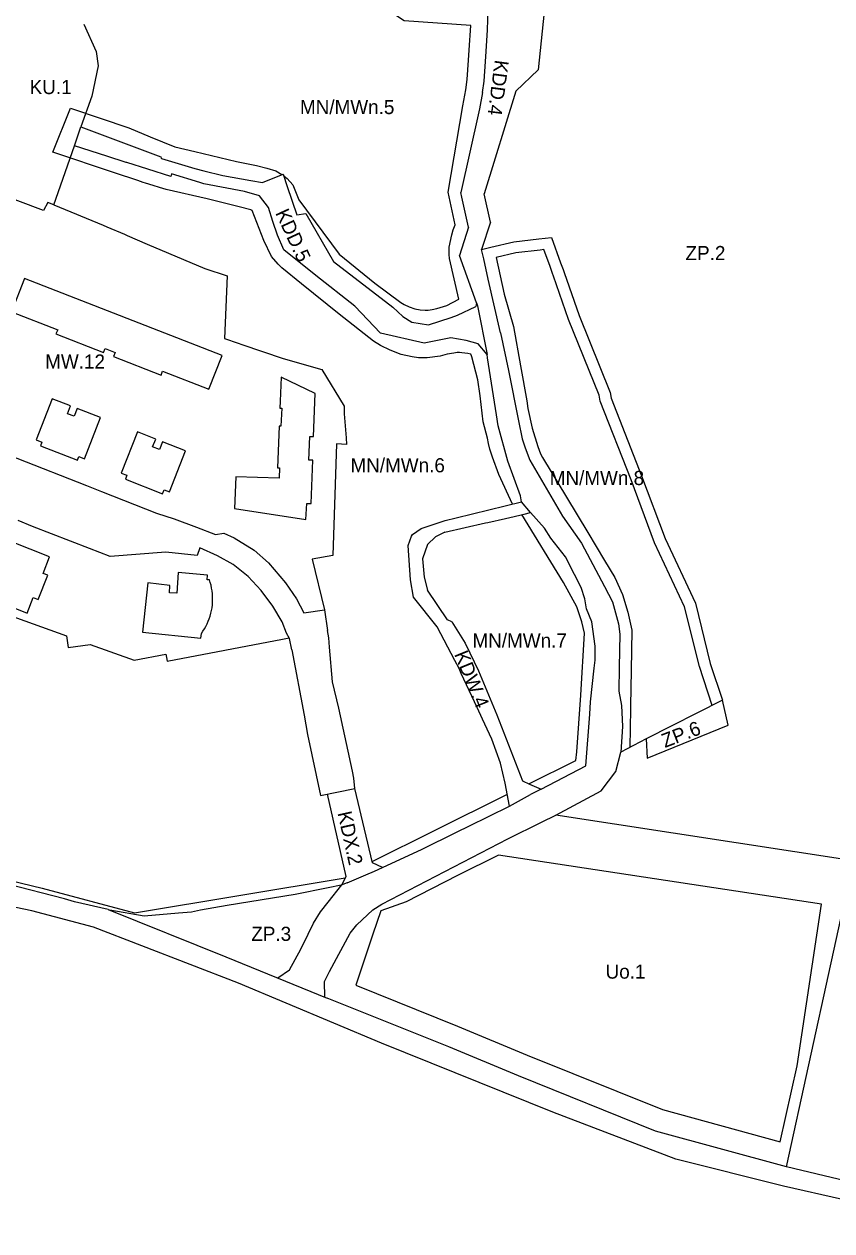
# Model space of a CAD drawing. Extents: x 7427074 to 7428708, y 5545888 to 5547145.
# Drawn here: x 7427601.2 to 7427887.2, y 5545922.5 to 5546349.6 of the extents above; entities that cross this region are included whole.
import ezdxf

# ---------------------------------------------------------------- set-up
doc = ezdxf.new("R2010")
doc.units = 0
for name, color, linetype in [('linie_rozgraniczajace', 7, 'Continuous'), ('linie_zabudowy_nieprzekraczalne', 7, 'Continuous'), ('linie_zabudowy_obowiazujace', 7, 'Continuous'), ('oznaczenia_przeznaczen', 7, 'Continuous')]:
    doc.layers.add(name, color=color, linetype=linetype)

msp = doc.modelspace()

# ---------------------------------------------------------------- linework, layer by layer
at = {"layer": 'linie_rozgraniczajace'}
for p, q in [((7427765.34, 5546347.61), (7427765.55, 5546354.65)), ((7427783.21, 5546333.36), (7427775.36, 5546325.89)), ((7427775.36, 5546325.89), (7427764.1, 5546289.55)), ((7427766.36, 5546279.48), (7427763.23, 5546269.84)), ((7427761.42, 5546250.98), (7427761.19, 5546249.62)), ((7427784.31, 5546078.85), (7427800.15, 5546087.09)), ((7427708.54, 5546077.03), (7427715.12, 5546047.85)), ((7427784.31, 5546078.85), (7427780.51, 5546076.87)), ((7427715.6, 5546045.7), (7427713.44, 5546044.8))]:
    msp.add_line(p, q, dxfattribs=at)
for points in [[(7427796.61, 5546466.79), (7427791.59, 5546414.49), (7427783.21, 5546333.36)], [(7427622.4, 5546349.58), (7427626.69, 5546339.86), (7427627.45, 5546334.8), (7427625.24, 5546324.12), (7427621.3, 5546313.22)], [(7427763.57, 5546325.38), (7427764.08, 5546329.36), (7427764.56, 5546336.41), (7427764.81, 5546339.92), (7427765.34, 5546347.61)], [(7427763.57, 5546325.38), (7427762.45, 5546319.55), (7427762.19, 5546318.5), (7427755.86, 5546289.94)], [(7427663.43, 5546293.51), (7427653.47, 5546296.56), (7427653.2, 5546295.66), (7427645.05, 5546298.22), (7427637.57, 5546300.58), (7427637.31, 5546300.66), (7427630.48, 5546302.84), (7427619.05, 5546306.5), (7427620.59, 5546311.05), (7427621.3, 5546313.22), (7427636.39, 5546307.59), (7427649.59, 5546302.67), (7427649.74, 5546302.14), (7427649.93, 5546302.08), (7427661.68, 5546298.43), (7427664.82, 5546297.67)], [(7427611.7, 5546285.64), (7427619.05, 5546306.5)], [(7427611.7, 5546285.64), (7427609.61, 5546286.47), (7427608.13, 5546283.63), (7427588.87, 5546290.82), (7427583.89, 5546292.85), (7427575.59, 5546296.26)], [(7427664.82, 5546297.67), (7427671.58, 5546296.04), (7427681.51, 5546294.25), (7427685.64, 5546293.55), (7427692.95, 5546296.51), (7427694.39, 5546292.07), (7427697.81, 5546282.09), (7427701.03, 5546282.56), (7427710.78, 5546265.62), (7427731.74, 5546249.35), (7427735.28, 5546246.13), (7427738.53, 5546244.14), (7427744.43, 5546243.1), (7427752.45, 5546245.69), (7427754.69, 5546246.55), (7427761.19, 5546249.62)], [(7427765.2, 5546232.62), (7427762.04, 5546236.48), (7427757.79, 5546237.61), (7427752.3, 5546238.55), (7427742.92, 5546236.65), (7427727.45, 5546240.25), (7427718.34, 5546249.77), (7427704.58, 5546260.65), (7427693.22, 5546269.69), (7427690.96, 5546274.84), (7427689.32, 5546279.73), (7427687.71, 5546284.73), (7427684.63, 5546288.81), (7427679.24, 5546290.32), (7427664.81, 5546293.09), (7427663.43, 5546293.51)], [(7427758.55, 5546277.73), (7427756.16, 5546288.39), (7427755.86, 5546289.94)], [(7427766.36, 5546279.48), (7427764.1, 5546289.55)], [(7427611.7, 5546285.64), (7427629.19, 5546278.47), (7427630.55, 5546277.88), (7427636.72, 5546275.2), (7427637.7, 5546274.77), (7427644.78, 5546271.7), (7427665.21, 5546263.09), (7427673.1, 5546260.46), (7427672.16, 5546238.35), (7427677.06, 5546236.65), (7427678.32, 5546236.22), (7427692.95, 5546231.24), (7427706.64, 5546227.31), (7427714.54, 5546214.32), (7427714.54, 5546211.6), (7427715.24, 5546203.17), (7427715.43, 5546200.75), (7427711.81, 5546201.08), (7427710.51, 5546161.49), (7427703.17, 5546160.22), (7427707.56, 5546142.3)], [(7427758.55, 5546277.73), (7427755.38, 5546267.67)], [(7427763.23, 5546269.84), (7427766.53, 5546270.62), (7427774.68, 5546272.56), (7427783.46, 5546273.58), (7427787.96, 5546274.11), (7427791.21, 5546265.15), (7427792.11, 5546262.68), (7427792.47, 5546261.7), (7427797.76, 5546246.42), (7427808.75, 5546219.26), (7427809.04, 5546217.19), (7427819.87, 5546189.7), (7427828.17, 5546167.55), (7427838.9, 5546144.63), (7427844.17, 5546123.31), (7427848.52, 5546110.3), (7427821.46, 5546096.59), (7427812.51, 5546091.92)], [(7427769.91, 5546240.35), (7427765.6, 5546259.27), (7427763.96, 5546266.47), (7427763.23, 5546269.84)], [(7427761.42, 5546250.98), (7427755.38, 5546267.67)], [(7427761.42, 5546250.98), (7427761.81, 5546249.91), (7427765.2, 5546232.62)], [(7427769.91, 5546240.35), (7427772.71, 5546227.01), (7427776.33, 5546209.18), (7427777.63, 5546202.83), (7427778.67, 5546199.67), (7427780.34, 5546195.25), (7427791.89, 5546175.44), (7427798.63, 5546165.93), (7427805.65, 5546152.59), (7427806.72, 5546150.55), (7427809.51, 5546145.16), (7427811.67, 5546137.37), (7427812.17, 5546133.62), (7427811.94, 5546122), (7427811.77, 5546113.47), (7427812.72, 5546108.46), (7427813.11, 5546100.93), (7427812.51, 5546091.92)], [(7427800.15, 5546087.09), (7427801.59, 5546105.41), (7427801.73, 5546109.73), (7427803.07, 5546121.64), (7427803.4, 5546124.5), (7427803.47, 5546129.47), (7427802.19, 5546138.03), (7427800.38, 5546142.69), (7427799.81, 5546146.23), (7427798.44, 5546150.14), (7427796.07, 5546154.83), (7427792.92, 5546161.01), (7427787.78, 5546167.63), (7427785.52, 5546171.22), (7427780.5, 5546176.68), (7427777.4, 5546180.54), (7427776.97, 5546182.61), (7427772.53, 5546194.89), (7427769.04, 5546207.36), (7427768.5, 5546211.32), (7427765.27, 5546231.45), (7427765.2, 5546232.62)], [(7427545.35, 5546216.74), (7427593.34, 5546198.01), (7427598.66, 5546195.91), (7427623.36, 5546186.25), (7427628.66, 5546184.17), (7427648.13, 5546176.53), (7427654.33, 5546174.53), (7427662.31, 5546171.58), (7427668.97, 5546168.95), (7427672, 5546169.44), (7427675.55, 5546167.81), (7427682.66, 5546163.4), (7427687.72, 5546158.91), (7427693.8, 5546151.78), (7427697.63, 5546146.12), (7427700.27, 5546141.2), (7427707.56, 5546142.3), (7427708.66, 5546134.98)], [(7427773.07, 5546072.84), (7427771.57, 5546080.91), (7427769.93, 5546087.96), (7427766.8, 5546096.49), (7427763.52, 5546103.57), (7427761.6, 5546107.7), (7427756.03, 5546119.73), (7427755.22, 5546121.46), (7427753.72, 5546124.32), (7427747.45, 5546136.21), (7427739.1, 5546146.82), (7427738.02, 5546152.93), (7427737.16, 5546165.1), (7427738.43, 5546168.3), (7427738.7, 5546168.98), (7427741.87, 5546171.02), (7427750.32, 5546173.84), (7427754.18, 5546174.83), (7427777.4, 5546180.54)], [(7427765.37, 5546173.23), (7427771.67, 5546174.63), (7427778.31, 5546176.17), (7427780.5, 5546176.68)], [(7427696, 5546128.15), (7427695.19, 5546132.1), (7427694.08, 5546134.06), (7427692.58, 5546137.99), (7427689.27, 5546143.55), (7427685.14, 5546149.1), (7427680.55, 5546154.05), (7427675.26, 5546158.33), (7427669.65, 5546161.45), (7427663.43, 5546164.17), (7427662.46, 5546161.48), (7427651.43, 5546162.66), (7427631.65, 5546161.11), (7427624.34, 5546163.93), (7427604.14, 5546171.77), (7427599.12, 5546173.84)], [(7427750.22, 5546169.82), (7427764.56, 5546173.05), (7427765.37, 5546173.23)], [(7427750.22, 5546169.82), (7427746.84, 5546168.11), (7427744.07, 5546165.37), (7427742.29, 5546160.32)], [(7427742.29, 5546160.32), (7427742.9, 5546153.79), (7427744.06, 5546149.23)], [(7427570.24, 5546149.62), (7427616.18, 5546133.08), (7427616.86, 5546128.9), (7427619.37, 5546129.27), (7427624.63, 5546130.04), (7427640.25, 5546124.41), (7427651.46, 5546126.57), (7427651.67, 5546125.45), (7427651.93, 5546124.11), (7427692.72, 5546131.94), (7427695.03, 5546132.38)], [(7427752.64, 5546138.06), (7427751.12, 5546138.69), (7427744.06, 5546149.23)], [(7427752.64, 5546138.06), (7427757.44, 5546130.45), (7427759.04, 5546127.1), (7427762.11, 5546120.67), (7427768.62, 5546105.11), (7427777.68, 5546081.7), (7427780.23, 5546080.6), (7427784.31, 5546078.85)], [(7427696, 5546128.15), (7427700.39, 5546104.95), (7427701.54, 5546098.19), (7427706.19, 5546076.54), (7427718.37, 5546079.07), (7427717.94, 5546082.75), (7427717.54, 5546085.17), (7427712.68, 5546107.49), (7427710.44, 5546116.81), (7427709.36, 5546129.04), (7427709.07, 5546132.32), (7427708.66, 5546134.98)], [(7427821.46, 5546096.59), (7427821.82, 5546089.79), (7427850.56, 5546101.47), (7427848.52, 5546110.3)], [(7427707.71, 5546005.16), (7427707.6, 5546010.68), (7427709.39, 5546014.27), (7427716.65, 5546027.82), (7427719.08, 5546030.8), (7427724.66, 5546036.09), (7427727.93, 5546038.11), (7427772.51, 5546061.18), (7427784.45, 5546067.14), (7427789.45, 5546069.63), (7427805.58, 5546078.22), (7427810.7, 5546085.09), (7427812.51, 5546091.92)], [(7427728.1, 5546051.03), (7427724.63, 5546052.71), (7427718.95, 5546076.62), (7427718.37, 5546079.07)], [(7427741.94, 5546057.48), (7427754.55, 5546063.74), (7427758.69, 5546065.77), (7427773.07, 5546072.84), (7427780.51, 5546076.87)], [(7427871.13, 5545945.16), (7427894.95, 5546053.41), (7427789.45, 5546069.63)], [(7427715.6, 5546045.7), (7427722.28, 5546048.47), (7427725.33, 5546049.74), (7427741.94, 5546057.48)], [(7427631.03, 5546036.17), (7427619.07, 5546038.93), (7427615.51, 5546039.97), (7427595.29, 5546045.21), (7427578.57, 5546048.02)], [(7427715.12, 5546047.85), (7427713.71, 5546044.91)], [(7427911.89, 5545928.89), (7427870.1, 5545938.24), (7427831.94, 5545947.85), (7427788.48, 5545964.44), (7427727.81, 5545988.89), (7427677.19, 5546010.17), (7427625.84, 5546029.97), (7427604.02, 5546035.69), (7427575.52, 5546041.68), (7427542.04, 5546043.19), (7427510.38, 5546042.02), (7427490.71, 5546040.43), (7427471.03, 5546035.51), (7427448.97, 5546027.41), (7427402.2, 5546009.67), (7427266.44, 5545955.68)], [(7427713.44, 5546044.8), (7427708.84, 5546043.86), (7427697.16, 5546041.5), (7427673.12, 5546037.64), (7427663.68, 5546035.96), (7427660.48, 5546035.32), (7427655.92, 5546034.91), (7427643.71, 5546033.81), (7427631.63, 5546035.93)], [(7427691.01, 5546012), (7427695.24, 5546014.9), (7427699.16, 5546022.18), (7427701.76, 5546027.49), (7427703.73, 5546031.33), (7427706.14, 5546035.36), (7427708.92, 5546038.86), (7427713.71, 5546044.91)], [(7427631.03, 5546036.17), (7427672.63, 5546019.51), (7427708.58, 5546004.81)], [(7427871.17, 5545945.15), (7427824.74, 5545957.78), (7427776.28, 5545977.29), (7427751.62, 5545987.57), (7427708.58, 5546004.81)], [(7428014.04, 5545935.57), (7427999.45, 5545930.71), (7427996.08, 5545928.85), (7427985.45, 5545925.51), (7427970.52, 5545922.47), (7427966.73, 5545922.97), (7427956.33, 5545925.17), (7427947.31, 5545927.07), (7427939.92, 5545928.77), (7427871.17, 5545945.15)]]:
    msp.add_lwpolyline(points, dxfattribs=at)
at = {"layer": 'linie_zabudowy_nieprzekraczalne'}
for p, q in [((7427798.39, 5546112.08), (7427799.66, 5546134.01)), ((7427796.9, 5546091.98), (7427798.39, 5546112.08)), ((7427746.76, 5546064.25), (7427772.2, 5546076.88)), ((7427883.62, 5546038.16), (7427769.16, 5546055.42)), ((7427640.29, 5546035.01), (7427714.91, 5546047.42)), ((7427736.54, 5546038.95), (7427727.55, 5546035.73)), ((7427874.91, 5545980.93), (7427883.62, 5546038.16))]:
    msp.add_line(p, q, dxfattribs=at)
for points in [[(7427751.37, 5546290.13), (7427756.55, 5546320.62), (7427757.64, 5546326.33), (7427758.11, 5546329.95), (7427758.57, 5546336.83), (7427758.82, 5546340.34), (7427759.43, 5546349.06), (7427735.84, 5546350.7), (7427713.25, 5546365.58), (7427659.2, 5546370.84), (7427656.06, 5546369.32), (7427642.12, 5546362.97), (7427642.11, 5546362.97), (7427633.54, 5546359.07), (7427621.01, 5546353.36), (7427620, 5546352.9), (7427590.07, 5546355.46), (7427588.43, 5546329.27)], [(7427774.14, 5546179.73), (7427769.36, 5546190.2), (7427767.13, 5546196.28), (7427766.18, 5546199.1), (7427765.66, 5546201.11), (7427765.28, 5546203.01), (7427763.78, 5546208.78), (7427762.75, 5546218.06), (7427761.83, 5546223.64), (7427759.76, 5546231.77), (7427759.63, 5546232.19), (7427759.39, 5546232.77), (7427758.29, 5546232.99), (7427756.23, 5546233.26), (7427755.36, 5546233.31), (7427754.55, 5546233.31), (7427753.34, 5546233.17), (7427750.99, 5546232.75), (7427748.53, 5546232.05), (7427743.97, 5546231.48), (7427740.87, 5546231.42), (7427738.65, 5546231.84), (7427734.73, 5546232.71), (7427730.82, 5546234.16), (7427727.45, 5546235.78), (7427724.9, 5546237.37), (7427712.73, 5546246.91), (7427699.47, 5546257.62), (7427692.52, 5546263.29), (7427691.19, 5546264.64), (7427688.79, 5546267.3), (7427686.13, 5546273.01), (7427681.95, 5546283.61), (7427681.78, 5546283.74), (7427681.49, 5546283.89), (7427677.33, 5546284.96), (7427666.01, 5546287.69), (7427651.53, 5546291.07), (7427649.19, 5546291.73), (7427646.92, 5546292.43), (7427644.24, 5546293.32), (7427643.39, 5546293.52), (7427641.55, 5546294.23), (7427633.25, 5546296.99), (7427611.44, 5546304.24), (7427617.6, 5546319.85), (7427638.34, 5546312.85), (7427645.9, 5546309.71), (7427654.59, 5546306.2), (7427661.62, 5546304.52), (7427676.4, 5546301.02), (7427683.48, 5546299.54), (7427687.22, 5546298.64), (7427690.35, 5546297.64), (7427692.54, 5546296.34), (7427692.95, 5546296.51), (7427693.15, 5546295.89), (7427694.4, 5546294.89), (7427696.36, 5546292.72), (7427698.52, 5546287.34), (7427712.83, 5546268.18), (7427725.43, 5546257.93), (7427734.56, 5546251.08), (7427735.85, 5546250.3), (7427737.58, 5546249.54), (7427739.54, 5546248.85), (7427741.47, 5546248.48), (7427743.23, 5546248.31), (7427744.26, 5546248.35), (7427745.73, 5546248.61), (7427747.38, 5546248.96), (7427750.87, 5546249.97), (7427755.11, 5546252.26), (7427751.83, 5546266.67)], [(7427751.83, 5546266.67), (7427751.69, 5546268.04), (7427751.69, 5546269.33), (7427751.78, 5546270.67), (7427752.64, 5546274.97), (7427753.2, 5546276.8), (7427753.84, 5546278.6), (7427751.37, 5546290.13)], [(7427844.91, 5546108.47), (7427840.33, 5546122.19), (7427835.11, 5546143.29), (7427824.48, 5546166), (7427816.14, 5546188.27), (7427805.14, 5546216.17), (7427804.86, 5546218.22), (7427794.01, 5546245.01), (7427788.7, 5546260.36), (7427788.35, 5546261.31), (7427787.45, 5546263.78), (7427785.28, 5546269.77), (7427783.92, 5546269.61), (7427775.38, 5546268.61), (7427768.33, 5546266.94)], [(7427768.33, 5546266.94), (7427771.21, 5546254.03), (7427774.51, 5546242.56)], [(7427774.51, 5546242.56), (7427776.94, 5546228.68), (7427779.22, 5546216.2), (7427779.58, 5546213.56), (7427781.07, 5546206.56), (7427783.11, 5546200.09)], [(7427783.11, 5546200.09), (7427784.09, 5546197.54), (7427784.78, 5546196.18), (7427793.25, 5546182.1)], [(7427793.25, 5546182.1), (7427800.88, 5546169.62), (7427806.79, 5546159.69), (7427810.41, 5546153.74), (7427813.16, 5546147.71), (7427815, 5546141.45), (7427816.4, 5546135.08), (7427816.23, 5546120.86)], [(7427799.66, 5546134.01), (7427798.7, 5546138.01), (7427796.93, 5546143.34), (7427792.18, 5546151.93), (7427777.47, 5546175.99)], [(7427816.23, 5546120.86), (7427815.97, 5546108.26), (7427815.97, 5546107.28), (7427815.68, 5546093.57)], [(7427779.95, 5546080.73), (7427796.61, 5546088.97), (7427796.9, 5546091.98)], [(7427724.5, 5546053.22), (7427746.76, 5546064.25)], [(7427769.16, 5546055.42), (7427754.69, 5546048.22), (7427736.54, 5546038.95)], [(7427560.88, 5546052.32), (7427573.21, 5546051.03), (7427580.61, 5546049.97), (7427588.46, 5546048.42), (7427596.37, 5546046.51), (7427607.64, 5546043.77)], [(7427607.64, 5546043.77), (7427640.29, 5546035.01)], [(7427727.55, 5546035.73), (7427724.76, 5546027.49), (7427718.63, 5546009.4)], [(7427718.63, 5546009.4), (7427754.64, 5545994.98), (7427779.31, 5545984.69), (7427827.29, 5545965.38), (7427868.99, 5545954.03)], [(7427868.99, 5545954.03), (7427874.91, 5545980.93)]]:
    msp.add_lwpolyline(points, dxfattribs=at)
at = {"layer": 'linie_zabudowy_obowiazujace'}
for points in [[(7427601.39, 5546259.56), (7427596.79, 5546247.81), (7427613.18, 5546241.41), (7427612.51, 5546239.98), (7427629.37, 5546233.39), (7427629.91, 5546234.78), (7427633.47, 5546233.39), (7427632.91, 5546231.96), (7427649.75, 5546225.38), (7427650.28, 5546226.74), (7427666.68, 5546220.33), (7427671.34, 5546232.25)], [(7427691.93, 5546216.13), (7427691.82, 5546213.68), (7427692.43, 5546213.65), (7427692.15, 5546207.27), (7427691.58, 5546207.3), (7427690.94, 5546192.56), (7427691.69, 5546192.53), (7427691.5, 5546188.84), (7427676.25, 5546189.36), (7427675.77, 5546178.13), (7427701.03, 5546174.27), (7427701.39, 5546179.97), (7427702.84, 5546179.88), (7427703.41, 5546195.25), (7427702.05, 5546195.31), (7427702.35, 5546203.65), (7427703.73, 5546203.6), (7427704.32, 5546218.9), (7427692.3, 5546224.59)], [(7427628.27, 5546210.38), (7427620.07, 5546213.58), (7427618.98, 5546210.77), (7427616.61, 5546211.69), (7427617.7, 5546214.47), (7427611.18, 5546217.01), (7427605.51, 5546202.45), (7427607.51, 5546201.67), (7427606.98, 5546200.3), (7427620.08, 5546195.2), (7427620.6, 5546196.55), (7427622.58, 5546195.77)], [(7427658.39, 5546198.55), (7427650.21, 5546201.8), (7427649.11, 5546199), (7427646.74, 5546199.94), (7427647.85, 5546202.74), (7427641.42, 5546205.28), (7427635.65, 5546190.71), (7427637.61, 5546189.93), (7427637.08, 5546188.58), (7427650.26, 5546183.36), (7427650.82, 5546184.77), (7427652.65, 5546184.05)], [(7427666.14, 5546154.57), (7427655.76, 5546155.52), (7427655.33, 5546148.14), (7427652.73, 5546148.29), (7427652.88, 5546150.88), (7427645.03, 5546151.83), (7427643.16, 5546134.43), (7427663.8, 5546132.21), (7427663.99, 5546133.87), (7427664.56, 5546134.69), (7427665.09, 5546135.54), (7427665.58, 5546136.41), (7427666.03, 5546137.31), (7427666.44, 5546138.21), (7427666.78, 5546139.15), (7427667.09, 5546140.05), (7427667.38, 5546141.05), (7427667.59, 5546142.03), (7427667.77, 5546143.01), (7427667.89, 5546144.01), (7427667.96, 5546145), (7427667.99, 5546146), (7427667.98, 5546147), (7427667.91, 5546148), (7427667.79, 5546149), (7427667.63, 5546149.98), (7427667.41, 5546150.96), (7427667.15, 5546151.92), (7427666.82, 5546152.93), (7427666.01, 5546152.94)]]:
    msp.add_lwpolyline(points, close=True, dxfattribs=at)
msp.add_lwpolyline([(7427593.28, 5546144.7), (7427602.33, 5546141.13), (7427604.49, 5546146.62), (7427606.2, 5546145.94), (7427609.58, 5546154.5), (7427607.92, 5546155.15), (7427610.23, 5546161.04), (7427582.13, 5546172.11)], dxfattribs=at)

# ---------------------------------------------------------------- texts
at = {"layer": 'oznaczenia_przeznaczen'}
for s, rotation, p in [('KDD.4', 262.4488, (7427767.92, 5546337.12)), ('KDD.5', 294.8912, (7427690.09, 5546282.76)), ('KDW.4', 292.247, (7427753.44, 5546126.6)), ('ZP.6', 21.0212, (7427828.11, 5546093.36)), ('KDX.2', 282.4885, (7427712.17, 5546070.41))]:
    msp.add_text(s, height=5, rotation=rotation, dxfattribs=at).set_placement(p)
for s, p in [('KU.1', (7427603.18, 5546324.81)), ('MN/MWn.5', (7427698.91, 5546317.74)), ('ZP.2', (7427835.42, 5546266.06)), ('MW.12', (7427608.69, 5546227.66)), ('MN/MWn.6', (7427716.78, 5546190.95)), ('MN/MWn.8', (7427787.33, 5546186.45)), ('MN/MWn.7', (7427759.97, 5546128.91)), ('ZP.3', (7427681.66, 5546025.11)), ('Uo.1', (7427807.12, 5546011.74))]:
    msp.add_text(s, height=5, dxfattribs=at).set_placement(p)

doc.saveas('drawing.dxf')
